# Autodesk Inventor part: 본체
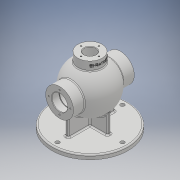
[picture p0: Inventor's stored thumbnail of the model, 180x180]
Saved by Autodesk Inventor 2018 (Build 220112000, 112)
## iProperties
Created: 2020-08
Part Number: 본체
Material: 일반
Document SubType Name: Modeling
Designer: USER
Density: 1 g/cm^3
Appearance: 기본값
Author: USER
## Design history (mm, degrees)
sketch "스케치1"
  geometry: L1 (0, 0)-(201.306, 0); L2 (0, 0)-(0, 31); L3 (136, 31)-(136, 0); L4 (0, 31)-(25.012, 31); L5 (110.988, 31)-(136, 31); L6 (0, 17.5)-(16, 17.5); L7 (16, 17.5)-(16, 18.5); L8 (16, 18.5)-(17.75, 18.5); L9 (17.75, 18.5)-(17.75, 17.5); L10 (17.75, 17.5)-(28.722, 17.5); L11 (107.278, 17.5)-(136, 17.5); A1 r 53 centre (68, 0) between (110.988, 31) and (25.012, 31); A2 r 43 centre (68, 0) between (107.278, 17.5) and (28.722, 17.5)
  constraints: 22 end point, 9 perpendicular, 4 point on circle, 4 point on line, 2 centre point, 1 coincident, 1 horizontal, 1 horizontal alignment, 1 vertical
  dimensions: "d0" = 106 diameter of A1; "d3" = 68 distance of A1.centre L1.start; "d4" = 136 distance between parallel lines of L2 L3; "d5" = 62 diameter of L4 L1; "d6" = 62 diameter of L5 L1; "d7" = 86 diameter of A2; "d9" = 37 diameter of L8 L1; "d10" = 35 diameter of L6 L1; "d11" = 35 diameter of L11 L1; "d12" = 1.75 distance of L7.end L8.end; "d13" = 16 distance of L6.start L6.end
revolve "회전1" sketch "스케치1" stored, may be unused: angle "d14" = 90 deg
node "작업 평면1"
sketch "스케치2"
  geometry: C1 r 27 at (0, 68); 1 further point
  constraints: 1 centre point, 1 vertical alignment
  dimensions: "d16" = 54 diameter of C1; "d17" = 68 distance of point (0, 0) C1.centre
extrude "돌출1" join sketch "스케치2" stored distance "d18" = 10; taper "d19" = 0 deg
sketch "스케치3"
  geometry: C1 r 13 at (0, 0); 1 further point
  constraints: 1 centre point
  dimensions: "d20" = 26 diameter of C1
extrude "돌출2" cut sketch "스케치3" stored distance "d21" = 10; taper "d22" = 0 deg
node "작업 평면2"
sketch "스케치4"
  geometry: C1 r 13 at (0, 68) reference; C2 r 85 at (0, 68); 1 further point
  constraints: 1 centre point, 1 coincident
  dimensions: "d24" = 170 diameter of C2
extrude "돌출3" join sketch "스케치4" distance "d25" = 10; taper "d26" = 0 deg
sketch "스케치5"
  geometry: L1 (-4, -52)-(4, -52); L2 (4, 52)-(-4, 52); L3 (43, -4)-(43, 4); L4 (-43, 4)-(-43, -4); L5 (-4, 52)-(-4, 4); L6 (-4, -4)-(-4, -52); L7 (-43, -4)-(-4, -4); L8 (4, -4)-(43, -4); L9 (43, 4)-(4, 4); L10 (-4, 4)-(-43, 4); L11 (4, -52)-(4, -4); L12 (4, 4)-(4, 52); 4 further points
  constraints: 24 end point, 10 parallel, 4 perpendicular, 3 horizontal, 2 midpoint, 1 horizontal alignment, 1 vertical alignment
  dimensions: "d27" = 8 distance of L4.start L4.end; "d28" = 8 distance of L2.start L2.end; "d29" = 104 distance of L1.end L2.start; "d30" = 86 distance of L3.end L4.start; "d31" = 43 distance from line of L3 point (0, 0); "d32" = 52 distance from line of L1 point (0, 0)
extrude "돌출4" join sketch "스케치5" stored distance "d33" = 10; taper "d34" = 0 deg
sketch "스케치6" dims "d35" = 145
  geometry: 3 further points
  constraints: 1 horizontal alignment, 2 other
hole "구멍1" sketch "스케치6" at (-72.5, 0) diameter "d36" = 9; stored, may be unused: countersink angle "d40" = 90 deg, drill point angle "d42" = 0 deg; dims "d37" = 6, "d38" = 4, "d39" = 2, "d41" = 10
sketch "스케치7" dims "d46" = 48
  geometry: 3 further points
  constraints: 1 coincident, 1 vertical alignment, 2 other
hole "구멍2" sketch "스케치7" at (0, 24) diameter "d47" = 3.242; stored, may be unused: countersink angle "d51" = 90 deg, drill point angle "d53" = 118 deg; dims "d48" = 12, "d49" = 4, "d50" = 2, "d52" = 15
sketch "스케치8" dims "d57" = 48
  geometry: 3 further points
  constraints: 1 coincident, 1 vertical alignment, 2 other
hole "구멍3" sketch "스케치8" at (0, -24) diameter "d58" = 3.242; stored, may be unused: countersink angle "d62" = 90 deg, drill point angle "d64" = 118 deg; dims "d59" = 12, "d60" = 4, "d61" = 2, "d63" = 15
sketch "스케치9" dims "d69" = 40
  geometry: 3 further points
  constraints: 1 horizontal alignment, 2 other
hole "구멍4" sketch "스케치9" at (-20, 0) diameter "d70" = 3.242; stored, may be unused: countersink angle "d74" = 90 deg, drill point angle "d76" = 118 deg; dims "d71" = 12, "d72" = 4, "d73" = 2, "d75" = 15
node "작업 평면3"
sketch "스케치11"
  geometry: L1 (-27, 0)-(27, 0) reference; 2 further points
  constraints: 1 other
  dimensions: "d80" = 9 distance from line of L1 point (0, -9); "d81" = 27 horizontal distance of L1.start point (0, -9)
feature "엠보싱1" sketch "스케치11" dims "d82" = 0.5, "d83" = 0
chamfer "모따기1" distance "d84" = 1; stored, may be unused: second distance "d85" = 2, angle "d86" = 45 deg
fillet "모깎기1" dims "d87" = 3
node "솔리드1"
pattern_circular "원형 패턴1" dims angle "d44" = 360 deg
pattern_circular "원형 패턴2" dims angle "d55" = 360 deg
pattern_circular "원형 패턴3" dims angle "d66" = 360 deg
pattern_circular "원형 패턴4" dims angle "d78" = 360 deg
other parameters: "d2" = 62, "d15" = 65, "d23" = -85
